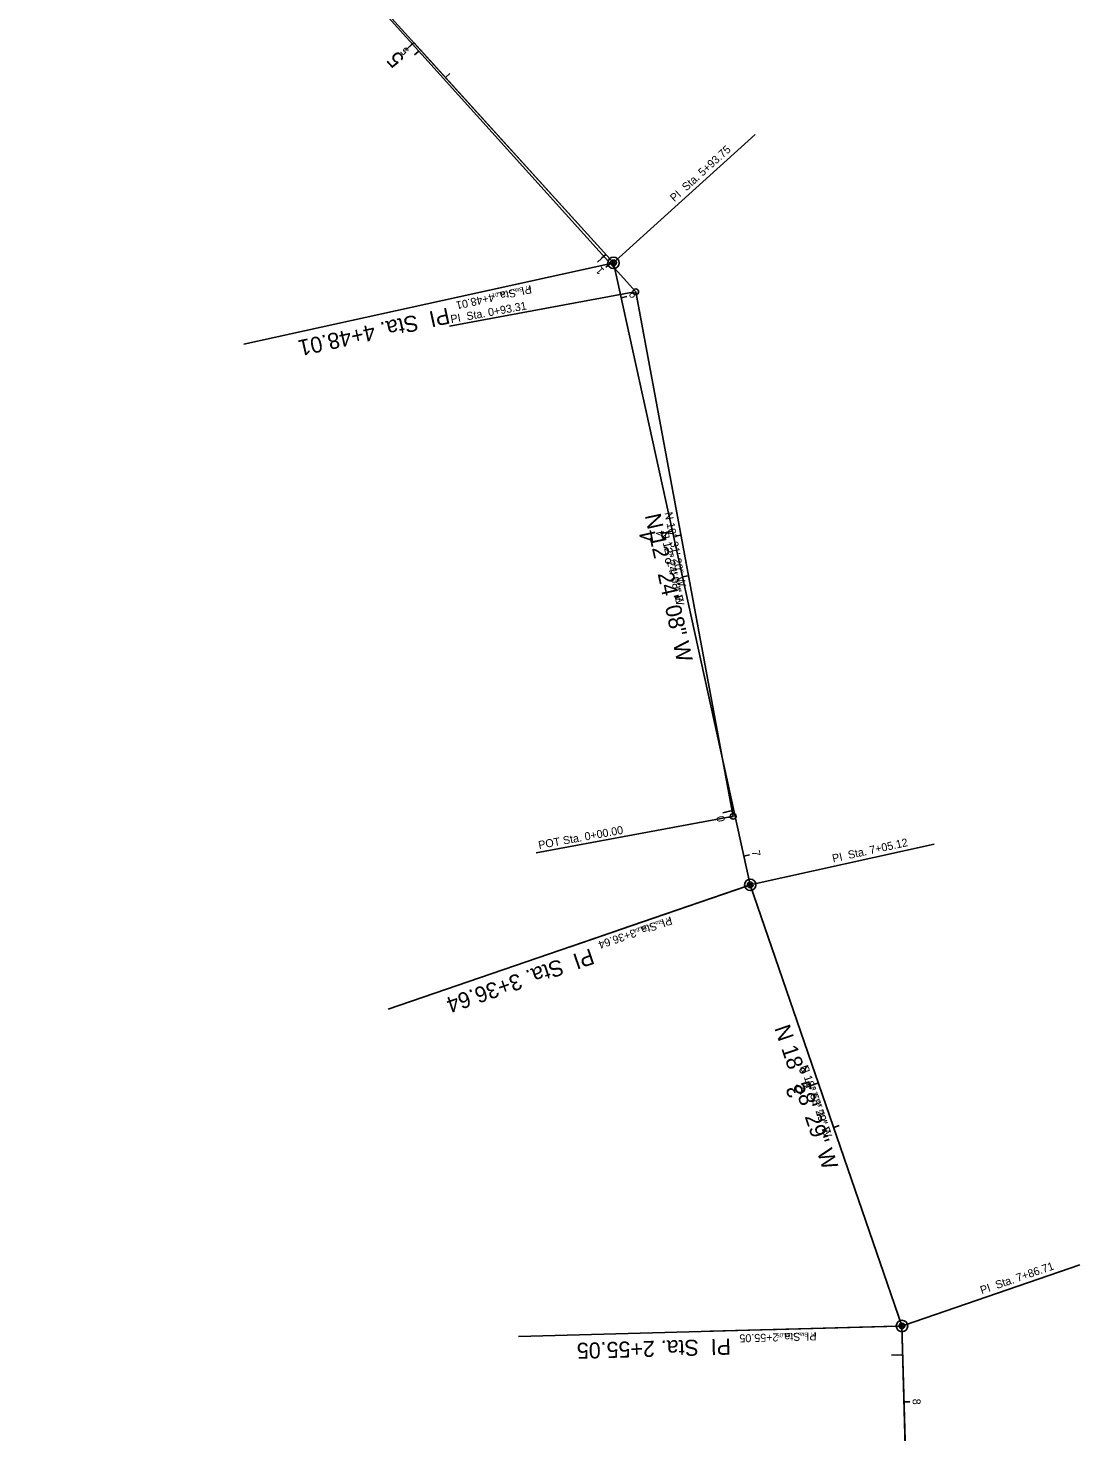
# Model space of a CAD drawing. Extents: x 2261207 to 2264340, y 653057 to 655601.
# Drawn here: x 2261561.3 to 2261745.2, y 654983.1 to 655228.6 of the extents above; entities that cross this region are included whole.
import ezdxf

# ---------------------------------------------------------------- set-up
doc = ezdxf.new("R2010")
doc.units = 0
for name, color, linetype in [('CL_X_Construction', 7, 'Continuous'), ('Default', 7, 'Continuous'), ('GE_X_CL_10', 7, 'Continuous'), ('GE_X_CL_20', 7, 'Continuous'), ('GE_X_CL_5', 7, 'Continuous'), ('SC_Scratch1', 7, 'Continuous'), ('SC_Scratch10', 7, 'Continuous'), ('SC_Scratch2', 7, 'Continuous'), ('SC_Scratch5', 7, 'Continuous')]:
    doc.layers.add(name, color=color, linetype=linetype)

msp = doc.modelspace()

# ---------------------------------------------------------------- linework, layer by layer
at = {"layer": 'CL_X_Construction'}
for p, q in [((2261663.66, 655187.52), (2261565.65, 655295.67)), ((2261663.66, 655187.52), (2261565.65, 655295.67)), ((2261687.58, 655078.76), (2261663.66, 655187.52)), ((2261687.58, 655078.76), (2261663.66, 655187.52)), ((2261714.11, 655001.6), (2261687.58, 655078.76)), ((2261714.11, 655001.6), (2261687.58, 655078.76)), ((2261716.47, 654914.99), (2261714.11, 655001.6)), ((2261716.47, 654914.99), (2261714.11, 655001.6))]:
    msp.add_line(p, q, dxfattribs=at)
at = {"layer": 'Default'}
msp.add_lwpolyline([(2261628.76, 655226.06), (2261663.66, 655187.52), (2261687.58, 655078.76), (2261687.58, 655078.76), (2261714.11, 655001.6), (2261716.47, 654914.99), (2261743.19, 654850.14), (2261734, 654813.88), (2261695.57, 654766.68)], dxfattribs=at)
at = {"layer": 'GE_X_CL_10'}
for p, q in [((2261663.66, 655187.52), (2261565.65, 655295.67)), ((2261628.75, 655226.05), (2261628.01, 655225.38)), ((2261662.33, 655189), (2261661.58, 655188.33)), ((2261663.17, 655187.42), (2261631.34, 655180.42)), ((2261687.58, 655078.76), (2261663.66, 655187.52)), ((2261673.97, 655140.63), (2261673, 655140.42)), ((2261684.71, 655091.8), (2261683.73, 655091.59)), ((2261687.11, 655078.59), (2261655.92, 655067.87)), ((2261714.11, 655001.6), (2261687.58, 655078.76)), ((2261699.49, 655044.1), (2261698.55, 655043.78)), ((2261713.61, 655001.58), (2261680.59, 655000.68)), ((2261716.47, 654914.99), (2261714.11, 655001.6)), ((2261714.25, 654996.55), (2261713.25, 654996.52))]:
    msp.add_line(p, q, dxfattribs=at)
for centre in [(2261663.66, 655187.52), (2261687.58, 655078.76), (2261714.11, 655001.6)]:
    msp.add_circle(centre, 0.5, dxfattribs=at)
at = {"layer": 'GE_X_CL_20'}
for p, q in [((2261663.66, 655187.52), (2261565.65, 655295.67)), ((2261663.66, 655187.52), (2261565.65, 655295.67)), ((2261628.75, 655226.05), (2261627.27, 655224.7)), ((2261628.75, 655226.05), (2261627.27, 655224.7)), ((2261628.75, 655226.05), (2261627.27, 655224.7)), ((2261628.75, 655226.05), (2261627.27, 655224.7)), ((2261662.33, 655189), (2261660.84, 655187.66)), ((2261662.33, 655189), (2261660.84, 655187.66)), ((2261662.33, 655189), (2261660.84, 655187.66)), ((2261662.33, 655189), (2261660.84, 655187.66)), ((2261662.68, 655187.31), (2261599.02, 655173.31)), ((2261662.68, 655187.31), (2261599.02, 655173.31)), ((2261662.68, 655187.31), (2261599.02, 655173.31)), ((2261662.68, 655187.31), (2261599.02, 655173.31)), ((2261687.58, 655078.76), (2261663.66, 655187.52)), ((2261687.58, 655078.76), (2261663.66, 655187.52)), ((2261673.97, 655140.63), (2261672.02, 655140.2)), ((2261673.97, 655140.63), (2261672.02, 655140.2)), ((2261673.97, 655140.63), (2261672.02, 655140.2)), ((2261673.97, 655140.63), (2261672.02, 655140.2)), ((2261684.71, 655091.8), (2261682.76, 655091.37)), ((2261684.71, 655091.8), (2261682.76, 655091.37)), ((2261684.71, 655091.8), (2261682.76, 655091.37)), ((2261684.71, 655091.8), (2261682.76, 655091.37)), ((2261686.63, 655078.43), (2261624.26, 655056.99)), ((2261686.63, 655078.43), (2261624.26, 655056.99)), ((2261686.63, 655078.43), (2261624.26, 655056.99)), ((2261686.63, 655078.43), (2261624.26, 655056.99)), ((2261714.11, 655001.6), (2261687.58, 655078.76)), ((2261714.11, 655001.6), (2261687.58, 655078.76)), ((2261699.49, 655044.1), (2261697.6, 655043.45)), ((2261699.49, 655044.1), (2261697.6, 655043.45)), ((2261699.49, 655044.1), (2261697.6, 655043.45)), ((2261699.49, 655044.1), (2261697.6, 655043.45)), ((2261713.11, 655001.57), (2261647.07, 654999.77)), ((2261713.11, 655001.57), (2261647.07, 654999.77)), ((2261713.11, 655001.57), (2261647.07, 654999.77)), ((2261713.11, 655001.57), (2261647.07, 654999.77)), ((2261716.47, 654914.99), (2261714.11, 655001.6)), ((2261716.47, 654914.99), (2261714.11, 655001.6)), ((2261714.25, 654996.55), (2261712.25, 654996.49)), ((2261714.25, 654996.55), (2261712.25, 654996.49)), ((2261714.25, 654996.55), (2261712.25, 654996.49)), ((2261714.25, 654996.55), (2261712.25, 654996.49))]:
    msp.add_line(p, q, dxfattribs=at)
for centre in [(2261663.66, 655187.52), (2261663.66, 655187.52), (2261663.66, 655187.52), (2261663.66, 655187.52), (2261687.58, 655078.76), (2261687.58, 655078.76), (2261687.58, 655078.76), (2261687.58, 655078.76), (2261714.11, 655001.6), (2261714.11, 655001.6), (2261714.11, 655001.6), (2261714.11, 655001.6)]:
    msp.add_circle(centre, 1, dxfattribs=at)
at = {"layer": 'GE_X_CL_5'}
for p, q in [((2261663.66, 655187.52), (2261565.65, 655295.67)), ((2261628.75, 655226.05), (2261628.01, 655225.38)), ((2261662.33, 655189), (2261661.58, 655188.33)), ((2261663.17, 655187.42), (2261640.37, 655182.4)), ((2261687.58, 655078.76), (2261663.66, 655187.52)), ((2261673.97, 655140.63), (2261673, 655140.42)), ((2261684.71, 655091.8), (2261683.73, 655091.59)), ((2261687.11, 655078.59), (2261664.67, 655070.88)), ((2261714.11, 655001.6), (2261687.58, 655078.76)), ((2261699.49, 655044.1), (2261698.55, 655043.78)), ((2261713.61, 655001.58), (2261690.03, 655000.94)), ((2261716.47, 654914.99), (2261714.11, 655001.6)), ((2261714.25, 654996.55), (2261713.25, 654996.52))]:
    msp.add_line(p, q, dxfattribs=at)
for centre in [(2261663.66, 655187.52), (2261687.58, 655078.76), (2261714.11, 655001.6)]:
    msp.add_circle(centre, 0.25, dxfattribs=at)
at = {"layer": 'SC_Scratch1'}
for p, q in [((2261565.65, 655295.67), (2261663.66, 655187.52)), ((2261663.66, 655187.52), (2261687.58, 655078.76)), ((2261687.58, 655078.76), (2261714.11, 655001.6)), ((2261714.11, 655001.6), (2261716.47, 654914.99))]:
    msp.add_line(p, q, dxfattribs=at)
at = {"layer": 'SC_Scratch10'}
for p, q in [((2261565.65, 655295.67), (2261663.66, 655187.52)), ((2261663.66, 655187.52), (2261687.58, 655078.76)), ((2261687.58, 655078.76), (2261714.11, 655001.6)), ((2261714.11, 655001.6), (2261716.47, 654914.99))]:
    msp.add_line(p, q, dxfattribs=at)
at = {"layer": 'SC_Scratch2'}
for p, q in [((2261565.65, 655295.67), (2261663.66, 655187.52)), ((2261634.28, 655219.95), (2261635.02, 655220.62)), ((2261634.28, 655219.95), (2261635.02, 655220.62)), ((2261664.03, 655187.86), (2261688.44, 655209.98)), ((2261664.03, 655187.86), (2261688.44, 655209.98)), ((2261663.66, 655187.52), (2261687.58, 655078.76)), ((2261665, 655181.42), (2261665.98, 655181.64)), ((2261665, 655181.42), (2261665.98, 655181.64)), ((2261675.74, 655132.59), (2261676.72, 655132.81)), ((2261675.74, 655132.59), (2261676.72, 655132.81)), ((2261688.07, 655078.86), (2261719.77, 655085.84)), ((2261688.07, 655078.86), (2261719.77, 655085.84)), ((2261686.48, 655083.76), (2261687.46, 655083.97)), ((2261686.48, 655083.76), (2261687.46, 655083.97)), ((2261687.58, 655078.76), (2261714.11, 655001.6)), ((2261702.17, 655036.32), (2261703.12, 655036.64)), ((2261702.17, 655036.32), (2261703.12, 655036.64)), ((2261714.58, 655001.76), (2261745.23, 655012.3)), ((2261714.58, 655001.76), (2261745.23, 655012.3)), ((2261714.11, 655001.6), (2261716.47, 654914.99)), ((2261714.47, 654988.32), (2261715.47, 654988.34)), ((2261714.47, 654988.32), (2261715.47, 654988.34))]:
    msp.add_line(p, q, dxfattribs=at)
for centre in [(2261663.66, 655187.52), (2261663.66, 655187.52), (2261687.58, 655078.76), (2261687.58, 655078.76), (2261714.11, 655001.6), (2261714.11, 655001.6)]:
    msp.add_circle(centre, 0.5, dxfattribs=at)
at = {"layer": 'SC_Scratch5'}
for p, q in [((2261667.55, 655182.48), (2261561.27, 655300.36)), ((2261629.59, 655224.58), (2261628.84, 655223.91)), ((2261629.59, 655224.58), (2261628.84, 655223.91)), ((2261629.59, 655224.58), (2261628.84, 655223.91)), ((2261663.07, 655187.44), (2261662.32, 655186.77)), ((2261663.07, 655187.44), (2261662.32, 655186.77)), ((2261663.07, 655187.44), (2261662.32, 655186.77)), ((2261667.05, 655182.39), (2261634.97, 655176.43)), ((2261667.05, 655182.39), (2261634.97, 655176.43)), ((2261667.05, 655182.39), (2261634.97, 655176.43)), ((2261684.59, 655090.73), (2261667.55, 655182.48)), ((2261675.46, 655139.89), (2261674.47, 655139.71)), ((2261675.46, 655139.89), (2261674.47, 655139.71)), ((2261675.46, 655139.89), (2261674.47, 655139.71)), ((2261684.09, 655090.64), (2261650.13, 655084.33)), ((2261684.09, 655090.64), (2261650.13, 655084.33)), ((2261684.09, 655090.64), (2261650.13, 655084.33)), ((2261684.59, 655090.73), (2261683.6, 655090.55)), ((2261684.59, 655090.73), (2261683.6, 655090.55)), ((2261684.59, 655090.73), (2261683.6, 655090.55))]:
    msp.add_line(p, q, dxfattribs=at)
for centre in [(2261667.55, 655182.48), (2261667.55, 655182.48), (2261667.55, 655182.48), (2261684.59, 655090.73), (2261684.59, 655090.73), (2261684.59, 655090.73)]:
    msp.add_circle(centre, 0.5, dxfattribs=at)

# ---------------------------------------------------------------- texts
at = {"layer": 'GE_X_CL_10'}
for s, rotation, p in [('5', 132.1843, (2261628, 655224.64)), ('PI  Sta. 4+48.01', 192.4021, (2261649.16, 655183.62)), ('4', 102.4021, (2261672.62, 655139.81)), ('N 12%%d 24\' 08" W', 282.4021, (2261671.87, 655140.42)), ('PI  Sta. 3+36.64', 198.9746, (2261673.62, 655073.22)), ('N 18%%d 58\' 29" W', 288.9746, (2261696.3, 655046.94)), ('3', 108.9746, (2261698.25, 655043.1)), ('PI  Sta. 2+55.05', 181.5641, (2261699.13, 655000.49))]:
    msp.add_text(s, height=1.4, rotation=rotation, dxfattribs=at).set_placement(p)
at = {"layer": 'GE_X_CL_20'}
for s, rotation, p in [('5', 132.1843, (2261627.24, 655223.24)), ('5', 132.1843, (2261627.24, 655223.24)), ('5', 132.1843, (2261627.24, 655223.24)), ('5', 132.1843, (2261627.24, 655223.24)), ('PI  Sta. 4+48.01', 192.4021, (2261634.66, 655179.71)), ('PI  Sta. 4+48.01', 192.4021, (2261634.66, 655179.71)), ('PI  Sta. 4+48.01', 192.4021, (2261634.66, 655179.71)), ('PI  Sta. 4+48.01', 192.4021, (2261634.66, 655179.71)), ('N 12%%d 24\' 08" W', 282.4021, (2261669.12, 655143.36)), ('4', 102.4021, (2261671.26, 655138.98)), ('4', 102.4021, (2261671.26, 655138.98)), ('4', 102.4021, (2261671.26, 655138.98)), ('4', 102.4021, (2261671.26, 655138.98)), ('PI  Sta. 3+36.64', 198.9746, (2261659.66, 655067.68)), ('PI  Sta. 3+36.64', 198.9746, (2261659.66, 655067.68)), ('PI  Sta. 3+36.64', 198.9746, (2261659.66, 655067.68)), ('PI  Sta. 3+36.64', 198.9746, (2261659.66, 655067.68)), ('N 18%%d 58\' 29" W', 288.9746, (2261691.75, 655053.7)), ('N 18%%d 58\' 29" W', 288.9746, (2261691.75, 655053.7)), ('3', 108.9746, (2261697.01, 655042.11)), ('3', 108.9746, (2261697.01, 655042.11)), ('3', 108.9746, (2261697.01, 655042.11)), ('3', 108.9746, (2261697.01, 655042.11)), ('PI  Sta. 2+55.05', 181.5641, (2261684.16, 654999.38)), ('PI  Sta. 2+55.05', 181.5641, (2261684.16, 654999.38)), ('PI  Sta. 2+55.05', 181.5641, (2261684.16, 654999.38)), ('PI  Sta. 2+55.05', 181.5641, (2261684.16, 654999.38))]:
    msp.add_text(s, height=2.8, rotation=rotation, dxfattribs=at).set_placement(p)
at = {"layer": 'GE_X_CL_5'}
for s, rotation, p in [('5', 132.1843, (2261627.8, 655224.86)), ('PI  Sta. 4+48.01', 192.4021, (2261649.16, 655183.62)), ('4', 102.4021, (2261672.56, 655140.09)), ('N 12%%d 24\' 08" W', 282.4021, (2261673.41, 655136.66)), ('PI  Sta. 3+36.64', 198.9746, (2261673.62, 655073.22)), ('3', 108.9746, (2261698.16, 655043.37)), ('N 18%%d 58\' 29" W', 288.9746, (2261698.26, 655043.39)), ('PI  Sta. 2+55.05', 181.5641, (2261699.13, 655000.49))]:
    msp.add_text(s, height=0.7, rotation=rotation, dxfattribs=at).set_placement(p)
at = {"layer": 'SC_Scratch2'}
for s, rotation, p in [('PI  Sta. 5+93.75', 42.1843, (2261674.31, 655198.12)), ('PI  Sta. 5+93.75', 42.1843, (2261674.31, 655198.12)), ('6', 282.4021, (2261666.35, 655182.27)), ('6', 282.4021, (2261666.35, 655182.27)), ('S 12%%d 24\' 08" E', 282.4021, (2261671.9, 655140.3)), ('PI  Sta. 7+05.12', 12.4021, (2261702.08, 655082.66)), ('PI  Sta. 7+05.12', 12.4021, (2261702.08, 655082.66)), ('7', 282.4021, (2261687.82, 655084.63)), ('7', 282.4021, (2261687.82, 655084.63)), ('S 18%%d 58\' 29" E', 288.9746, (2261696.34, 655046.82)), ('PI  Sta. 7+86.71', 18.9746, (2261728.07, 655007.14)), ('PI  Sta. 7+86.71', 18.9746, (2261728.07, 655007.14)), ('8', 271.5641, (2261715.96, 654988.86)), ('8', 271.5641, (2261715.96, 654988.86))]:
    msp.add_text(s, height=1.4, rotation=rotation, dxfattribs=at).set_placement(p)
at = {"layer": 'SC_Scratch5'}
for s, rotation, p in [('1', 132.0375, (2261662.15, 655186.22)), ('1', 132.0375, (2261662.15, 655186.22)), ('1', 132.0375, (2261662.15, 655186.22)), ('PI  Sta. 0+93.31', 10.3446, (2261635.29, 655176.97)), ('N 10%%d 31\' 20" W', 280.5223, (2261672.59, 655143.82)), ('0', 100.5223, (2261683.21, 655089.91)), ('0', 100.5223, (2261683.21, 655089.91)), ('0', 100.5223, (2261683.21, 655089.91)), ('POT Sta. 0+00.00', 10.403, (2261650.65, 655085))]:
    msp.add_text(s, height=1.4, rotation=rotation, dxfattribs=at).set_placement(p)

doc.saveas('drawing.dxf')
